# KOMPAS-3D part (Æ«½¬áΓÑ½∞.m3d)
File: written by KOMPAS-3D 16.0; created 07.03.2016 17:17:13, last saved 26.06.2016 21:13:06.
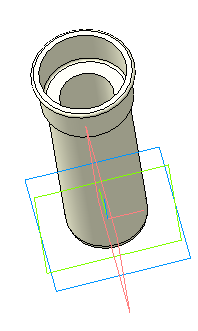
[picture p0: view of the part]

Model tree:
1. Эскиз:1
2. Операция выдавливания:1
     Расстояние 1 = 80.5
3. Скругление:1
     Радиус = 5
4. Эскиз:2
5. Операция выдавливания:2
     Расстояние 1 = 15
6. Эскиз:3
7. Операция выдавливания:3
     Расстояние 1 = 2
8. Эскиз:4
9. Вырезать элемент выдавливания:2
     Расстояние 1 = 16
10. Эскиз:5
11. Вырезать элемент выдавливания:3
     Расстояние 1 = 76
12. Фаска:1
     Угол = 45; Длина 1 = 2; Длина 2 = 2
13. Скругление:5
     Радиус = 1
14. Скругление:6
     Радиус = 1
15. Скругление:7
     Радиус = 1
16. Скругление:8
     Радиус = 1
